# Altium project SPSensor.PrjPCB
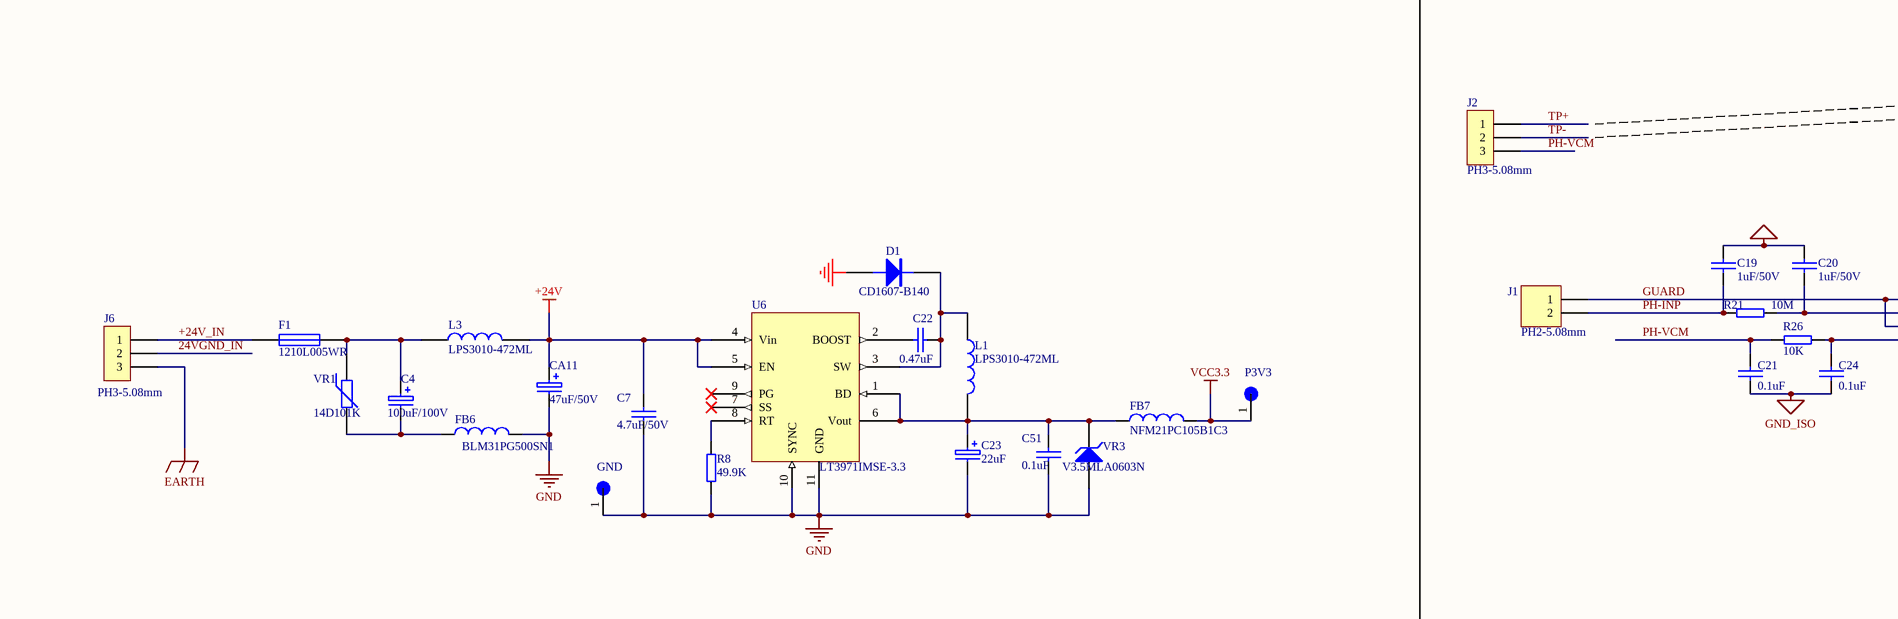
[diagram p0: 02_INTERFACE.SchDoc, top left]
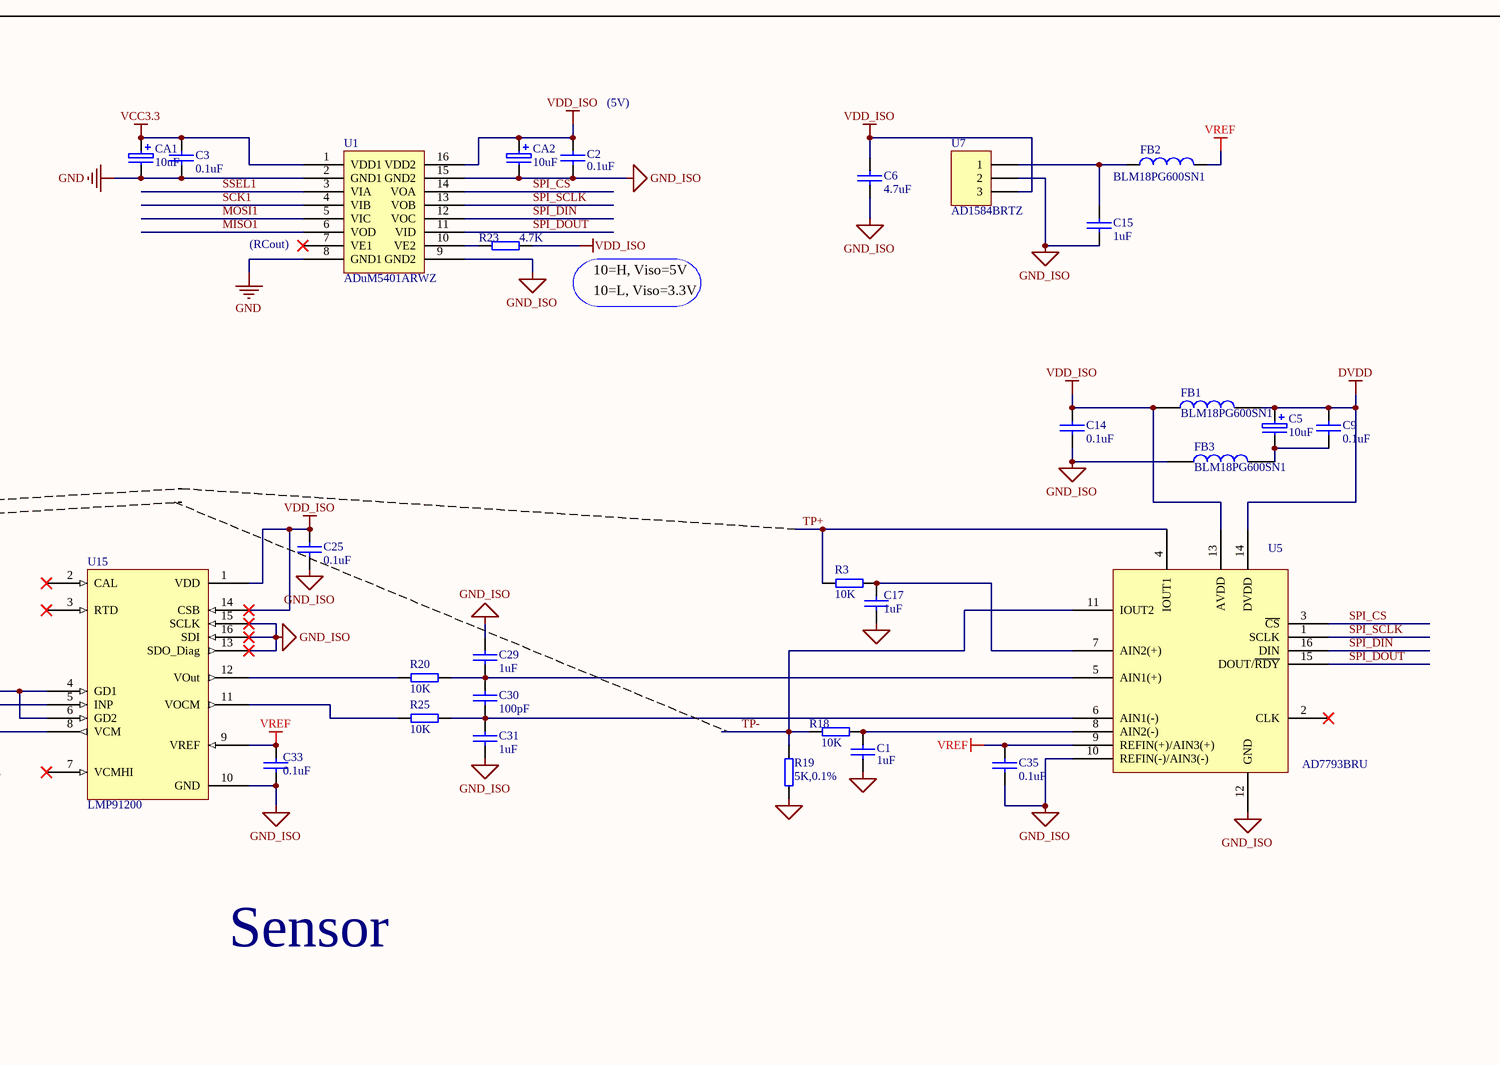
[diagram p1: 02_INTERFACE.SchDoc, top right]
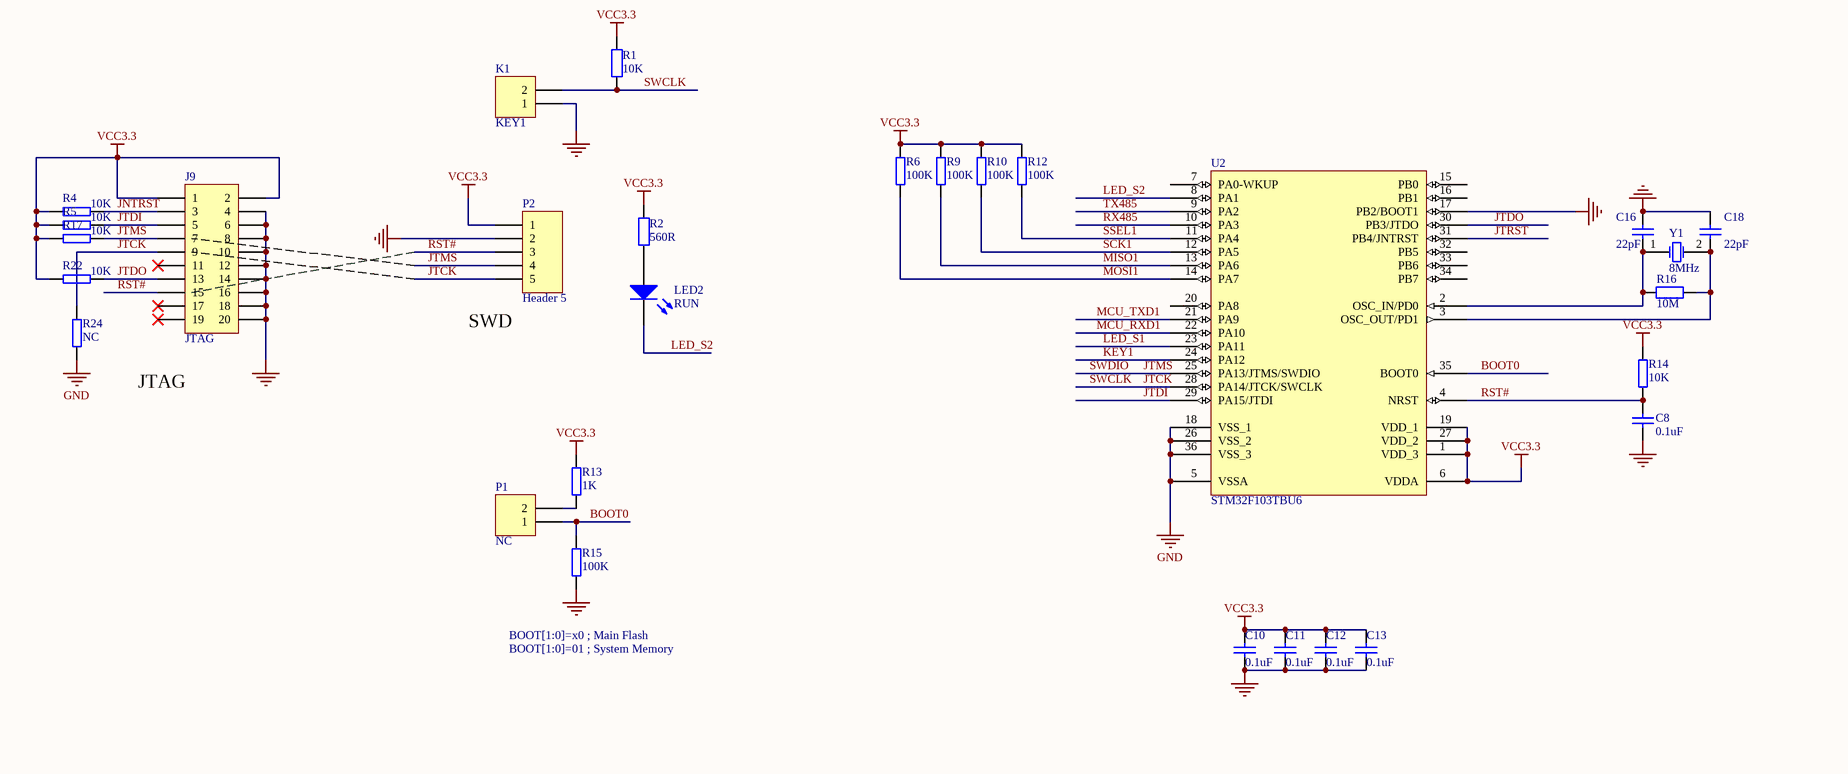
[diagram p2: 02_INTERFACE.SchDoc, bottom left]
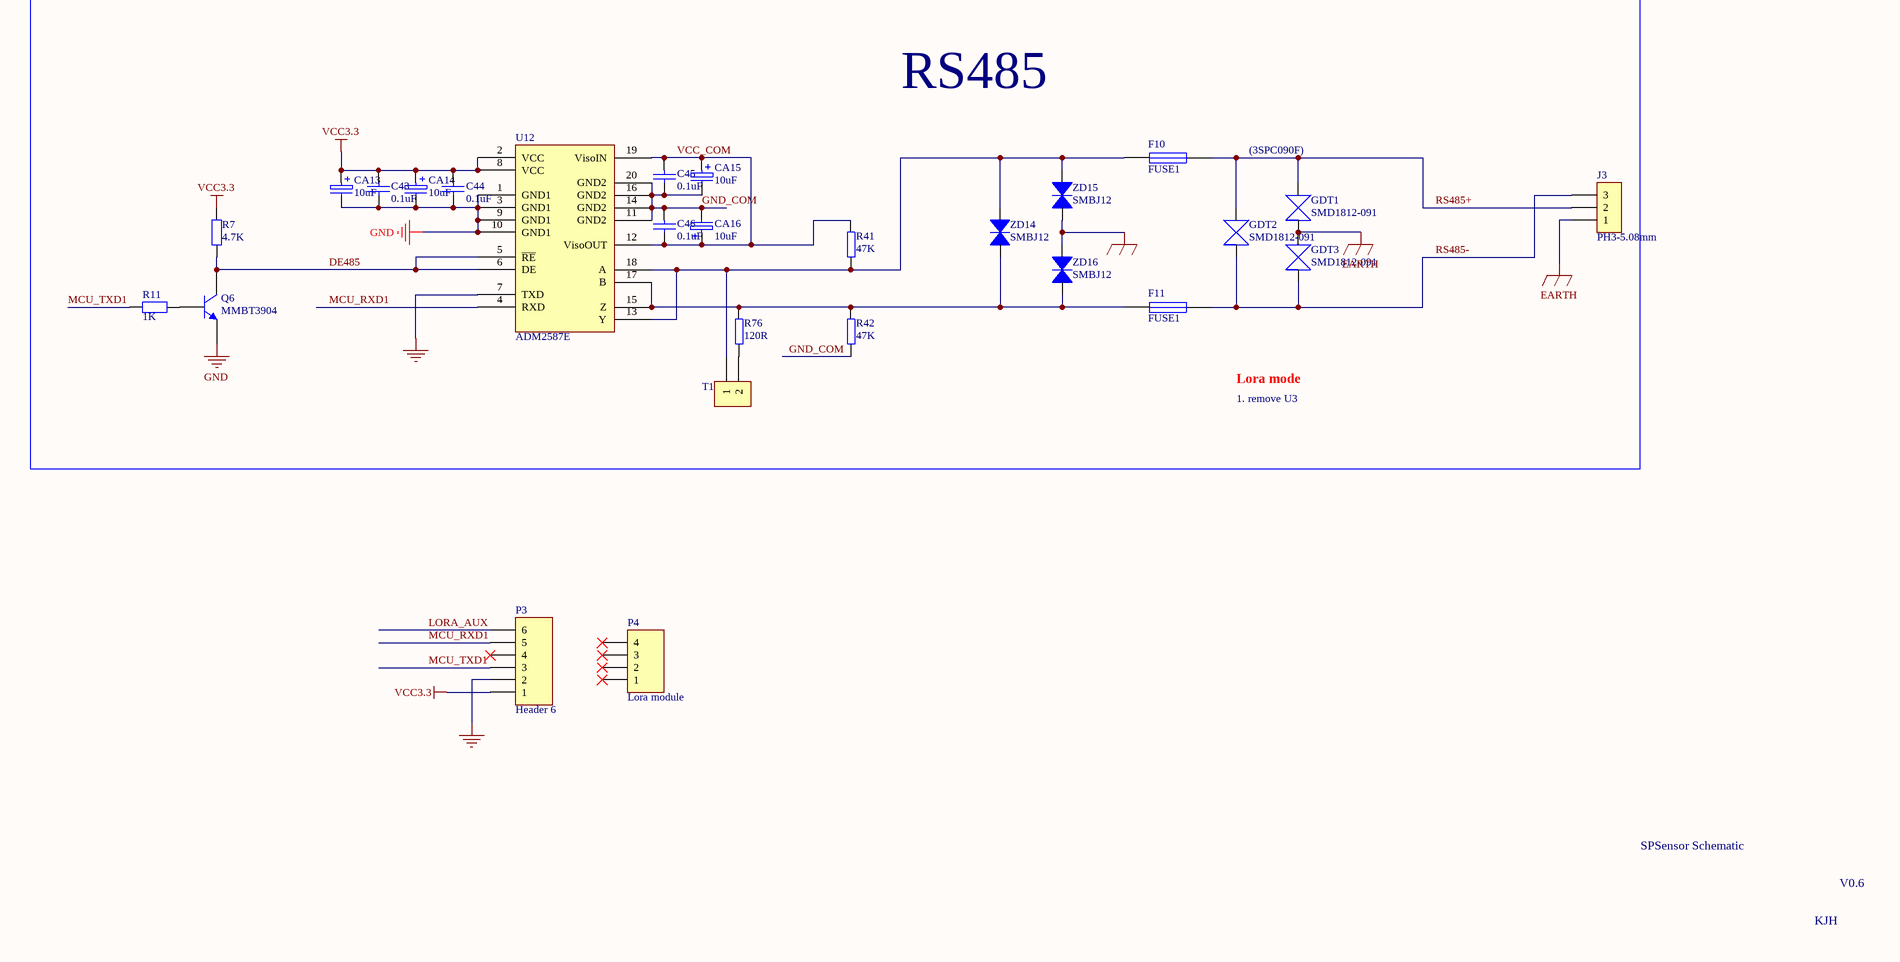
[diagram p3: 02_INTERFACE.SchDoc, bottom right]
1 sheet, 113 parts. Net scope: global (net labels, ports and power ports of the same name join across sheets).
Board file: SPSensor V0.7.PcbDoc

## Sheet 02_INTERFACE.SchDoc
size D; SheetNumber: 0; SheetTotal: 0

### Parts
C1  1uF  [SM0603]
C2  0.1uF  [SM0603]
C3  0.1uF  [SM0603]
C4  100uF/100V  [PCAP_3.5_8]
C5  10uF  [SM1206]
C6  4.7uF  [SM0603]
C7  4.7uF/50V  [SM1206]
C8  0.1uF  [SM0603]
C9  0.1uF  [SM0603]
C10  0.1uF  [SM0603]
C11  0.1uF  [SM0603]
C12  0.1uF  [SM0603]
C13  0.1uF  [SM0603]
C14  0.1uF  [SM0603]
C15  1uF  [SM0603]
C16  22pF  [SM0603]
C17  1uF  [SM0603]
C18  22pF  [SM0603]
C19  1uF/50V  [SM0603]
C20  1uF/50V  [SM0603]
C21  0.1uF  [SM0603]
C22  0.47uF  [SM0603]
C23  22uF  [SM1206]
C24  0.1uF  [SM0603]
C25  0.1uF  [SM0603]
C29  1uF  [SM0603]
C30  100pF  [SM0603]
C31  1uF  [SM0603]
C33  0.1uF  [SM0603]
C35  0.1uF  [SM0603]
C43  0.1uF  [SM0603]
C44  0.1uF  [SM0603]
C45  0.1uF  [SM0603]
C46  0.1uF  [SM0603]
C51  0.1uF  [SM0603]
CA1  10uF  [SM1206]
CA2  10uF  [SM1206]
CA11  47uF/50V  [D]
CA13  10uF  [SM1206]
CA14  10uF  [SM1206]
CA15  10uF  [SM1206]
CA16  10uF  [SM1206]
D1  CD1607-B140  [1206D]
F1  1210L005WR  [1808C]
F10  FUSE1  [SM0805]
F11  FUSE1  [SM0805]
FB1  BLM18PG600SN1  [SM0603]
FB2  BLM18PG600SN1  [SM0603]
FB3  BLM18PG600SN1  [SM0603]
FB6  BLM31PG500SN1  [1206]
FB7  NFM21PC105B1C3  [NFM21PC105]
GDT1  SMD1812-091  [1812]
GDT2  SMD1812-091  [1812]
GDT3  SMD1812-091  [1812]
GND  TestPoint  [test point]  (value not drawn)
J1  PH2-5.08mm  [PH2-5.08mm]
J2  PH3-5.08mm  [PH3-5.08mm]
J3  PH3-5.08mm  [PH3-5.08mm]
J6  PH3-5.08mm  [PH3-5.08mm]
J9  JTAG  [HDR2X10]
K1  KEY1  [HDR1x2]
L1  LPS3010-472ML  [LPS3010]
L3  LPS3010-472ML  [LPS3010]
LED2  RUN  [LED]
P1  NC  [SM0603]
P2  Header 5
P3  Header 6  [HDR1X6]
P3V3  TestPoint  [test point]  (value not drawn)
P4  Lora module
Q6  MMBT3904  [SOT23_N]
R1  10K  [SM0603]
R2  560R  [SM0603]
R3  10K  [SM0603]
R4  10K  [SM0603]
R5  10K  [SM0603]
R6  100K  [SM0603]
R7  4.7K  [SM0603]
R8  49.9K  [SM0603]
R9  100K  [SM0603]
R10  100K  [SM0603]
R11  1K  [SM0603]
R12  100K  [SM0603]
R13  1K  [SM0603]
R14  10K  [SM0603]
R15  100K  [SM0603]
R16  10M  [SM0603]
R17  10K  [SM0603]
R18  10K  [SM0603]
R19  5K,0.1%  [SM0603]
R20  10K  [SM0603]
R21  10M  [SM0603]
R22  10K  [SM0603]
R23  4.7K  [SM0603]
R24  NC  [SM0603]
R25  10K  [SM0603]
R26  10K  [SM0603]
R41  47K  [SM0603]
R42  47K  [SM0603]
R76  120R  [SM0603]
T1  (no value)  [SM0603]
U1  ADuM5401ARWZ  [ADUM1401]
U2  STM32F103TBU6  [VFQN36_V]
U5  AD7793BRU  [AD7793]
U6  LT3971IMSE-3.3  [LT3971]
U7  AD1584BRTZ  [SOT-23]
U12  ADM2587E  [SOL-20]
U15  LMP91200  [LMP91200]
VR1  14D101K  [RAD-0.3]
VR3  V3.5MLA0603N  [SM0603]
Y1  8MHz  [CY5.4X4.6]
ZD14  SMBJ12  [ZD]
ZD15  SMBJ12  [ZD]
ZD16  SMBJ12  [ZD]

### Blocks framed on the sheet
Sensor: C1-C3 C5 C6 C9 C14 C15 C17 C19-C21 C24 C25 C29-C31 C33 C35 CA1 CA2 FB1-FB3 J1 J2 R3 R18-R21 R23 R25 R26 U1 U5 U7 U15
RS485: C43-C46 CA13-CA16 F10 F11 GDT1-GDT3 J3 Q6 R7 R11 R41 R42 R76 T1 U12 ZD14-ZD16

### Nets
+24V: C7.1 CA11.1 L3.2 U6.4(Vin) U6.5(EN)
DVDD: C5.1 C9.1 FB1.2 U5.14(DVDD)
EARTH: GDT1.1 GDT3.2 J3.1 J6.3 ZD15.2 ZD16.1
GND: C3.1 C7.2 C8.2 C10.2 C11.2 C12.2 C13.2 C16.2 C18.2 C23.2 C43.2 C44.2 C51.2 CA1.2 CA11.2 CA13.2 CA14.2 D1.1(A) FB6.2 GND.1 J9.4 J9.6 J9.8 J9.10 J9.12 J9.14 J9.16 J9.18 J9.20 K1.1 P2.2 P3.2 Q6.2(E) R8.1 R15.1 R24.1 U1.2(GND1) U1.8(GND1) U2.5(VSSA) U2.17(PB2/BOOT1) U2.18(VSS_1) U2.26(VSS_2) U2.36(VSS_3) U6.10(SYNC) U6.11(GND) U12.1(GND1) U12.3(GND1) U12.7(TXD) U12.9(GND1) U12.10(GND1) VR3.1(A)
GND_ISO: C1.2 C2.2 C6.2 C14.2 C15.2 C17.2 C19.2 C20.2 C21.2 C24.2 C25.2 C29.1 C31.2 C33.2 C35.2 CA2.2 FB3.1 R19.1 U1.9(GND2) U1.15(GND2) U5.10(REFIN(-)/AIN3(-)) U5.12(GND) U7.2 U15.10(GND) U15.13(SDO_Diag) U15.15(SCLK) U15.16(SDI)
VCC3.3: C3.2 C10.1 C11.1 C12.1 C13.1 C43.1 C44.1 CA1.1 CA13.1 CA14.1 FB7.2 J9.1 J9.2 P2.1 P3.1 P3V3.1 R1.1 R2.1 R4.1 R5.1 R6.1 R7.2 R9.1 R10.1 R12.1 R13.1 R14.1 R17.1 R22.1 U1.1(VDD1) U2.1(VDD_3) U2.6(VDDA) U2.19(VDD_1) U2.27(VDD_2) U12.2(VCC) U12.8(VCC)
VDD_ISO: C2.1 C6.1 C14.1 C25.1 CA2.1 FB1.1 R23.2 U1.16(VDD2) U5.13(AVDD) U7.3 U15.1(VDD) U15.14(CSB)
VREF: C33.1 C35.1 FB2.2 U5.9(REFIN(+)/AIN3(+)) U15.9(VREF)
24VGND_IN: J6.2
+24V_IN: F1.1 J6.1
BOOT0: P1.1 R15.2 U2.35(BOOT0)
DE485: Q6.3(C) R7.1 U12.5(~{RE}) U12.6(DE)
GND_COM: C45.2 C46.1 CA15.2 CA16.2 R42.2 U12.11(GND2) U12.14(GND2) U12.16(GND2) U12.20(GND2)
GUARD: J1.1 U15.4(GD1) U15.6(GD2)
JNTRST: J9.3 R4.2
JTCK: J9.9 K1.2 P2.5 R1.2 R24.2 U2.28(PA14/JTCK/SWCLK)  [also labelled SWCLK]
JTDI: J9.5 R5.2 U2.29(PA15/JTDI)
JTDO: J9.13 R22.2 U2.30(PB3/JTDO)
JTMS: J9.7 P2.4 R17.2 U2.25(PA13/JTMS/SWDIO)  [also labelled SWDIO]
JTRST: U2.31(PB4/JNTRST)
KEY1: U2.24(PA12)
LED_S1: U2.23(PA11)
LED_S2: LED2.2(K) U2.8(PA1)
LORA_AUX: P3.6
MCU_RXD1: P3.5 U2.22(PA10) U12.4(RXD)
MCU_TXD1: P3.3 R11.1 U2.21(PA9)
MISO1: R9.2 U1.6(VOD) U2.13(PA6)
MOSI1: R6.2 U1.5(VIC) U2.14(PA7)
PH-INP: C19.1 J1.2 R21.1
PH-VCM: C21.1 J2.3 R26.1
RS485+: F10.2 GDT1.2 GDT2.2 J3.2
RS485-: F11.2 GDT2.1 GDT3.1 J3.3
RST#: C8.1 J9.15 P2.3 R14.2 U2.4(NRST)
RX485: U2.10(PA3)
SCK1: R10.2 U1.4(VIB) U2.12(PA5)
SPI_CS: U1.14(VOA) U5.3(~{CS})
SPI_DIN: U1.12(VOC) U5.16(DIN)
SPI_DOUT: U1.11(VID) U5.15(DOUT/~{RDY})
SPI_SCLK: U1.13(VOB) U5.1(SCLK)
SSEL1: R12.2 U1.3(VIA) U2.11(PA4)
TP+: J2.1 R3.1 U5.4(IOUT1)
TP-: J2.2 R18.1 R19.2 U5.11(IOUT2)
TX485: U2.9(PA2)
VCC_COM: C45.1 C46.2 CA15.1 CA16.1 R41.1 U12.12(VisoOUT) U12.19(VisoIN)
NetC1_1: C1.1 R18.2 U5.8(AIN2(-))
NetC4_1: C4.1 F1.2 L3.1 VR1.1
NetC4_2: C4.2 FB6.1 VR1.2
NetC5_2: C5.2 C9.2 FB3.2
NetC15_1: C15.1 FB2.1 U7.1
NetC16_1: C16.1 R16.1 U2.2(OSC_IN/PD0) Y1.1(OSC1)
NetC17_1: C17.1 R3.2 U5.7(AIN2(+))
NetC18_1: C18.1 R16.2 U2.3(OSC_OUT/PD1) Y1.2(OSC2)
NetC20_1: C20.1 R21.2 U15.5(INP)
NetC22_1: C22.1 U6.2(BOOST)
NetC22_2: C22.2 D1.2(K) L1.1 U6.3(SW)
NetC23_1: C23.1 C51.1 FB7.1 L1.2 U6.1(BD) U6.6(Vout) VR3.2(K)
NetC24_1: C24.1 R26.2 U15.8(VCM)
NetC29_2: C29.2 C30.1 R20.2 U5.5(AIN1(+))
NetC30_2: C30.2 C31.1 R25.2 U5.6(AIN1(-))
NetF10_1: F10.1 R41.2 T1.1 U12.13(Y) U12.18(A) ZD14.1 ZD15.1
NetF11_1: F11.1 R42.1 R76.1 U12.15(Z) U12.17(B) ZD14.2 ZD16.2
NetLED2_1: LED2.1(A) R2.2
NetP1_2: P1.2 R13.2
NetQ6_1: Q6.1(B) R11.2
NetR8_2: R8.2 U6.8(RT)
NetR20_1: R20.1 U15.12(VOut)
NetR23_1: R23.1 U1.10(VE2)
NetR25_1: R25.1 U15.11(VOCM)
NetR76_2: R76.2 T1.2

Not connected (* = marked no-connect by the designer): J9 11* 17* 19*; P3 4*; P4 1* 2* 3* 4*; U1 7(VE1)*; U2 7(PA0-WKUP) 15(PB0) 16(PB1) 20(PA8) 32(PB5) 33(PB6) 34(PB7); U5 2(CLK)*; U6 7(SS)* 9(PG)*; U15 2(CAL)* 3(RTD)* 7(VCMHI)*

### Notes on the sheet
- (near C2) (5V)
- (near U1) (RCout)
- 10=H, Viso=5V
- 10=L, Viso=3.3V
- (near P2) SWD
- JTAG
- (near GDT1) (3SPC090F)
- BOOT[1:0]=x0 ; Main Flash
- BOOT[1:0]=01 ; System Memory
- 1. remove U3
- Lora mode
- SPSensor Schematic
- KJH
- V0.6

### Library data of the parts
C1 C6 C7 C9 C14 C15 C17 C19-C22 C24 C25 C29-C31 C33 C35 C51 = CAP: Capacitor
C2 C3 C43-C46 = CA: 电容
C4 = C: Capacitor
C5 CA11 CA13-CA16 = CAPE: 极性电容
C8 = Cap: Capacitor, X7R Ceramic
C10-C13 = Cap: Capacitor
C16 C18 = Cap: Capacitor; Value: 0.1uF
C23 = C: 极性电容
CA1 CA2 = CAPE: Capacitor
D1 = DIODE
F1 = FUSE1: Fuse, 50mA
F10 F11 = FUSE1: Fuse
FB1 FB3 L1 L3 = INDUCTOR
FB2 FB6 FB7 = Inductor: Code_IEC: 1005; Value: 10mH
GDT1-GDT3 = BT90
J1 K1 = Header 2: Header, 2-Pin
J2 J3 J6 = CON3: Connector
J9 = Header 10X2: Header, 10-Pin, Dual row
LED2 = LED0: Typical INFRARED GaAs LED
P1 = Header: Header, 2-Pin, 2.54mm, 排针
P2 = Header 5: Header, 5-Pin
P3 = Header 6: Header, 6-Pin
P4 = Header 4: Header, 4-Pin
Q6 = MMBT3904: NPN Switching Transistor
R1 R2 R7 R16 = Res2: Resistor; Value: 1K
R3-R6 R9 R10 R12 R17-R20 R22 R24-R26 = RES: 电阻
R8 R13-R15 R23 R41 R42 R76 = RE: 电阻
R11 = Res2: Resistor
R21 = RES: resistor
T1 = CON2: Connector
U1 = ADUM1401: 1Mbps Data Rate, 100ns Propagation delay
U2 = STM32F103T8U6: STM32 ARM-based 32-bit MCU with 64 Kbytes Flash, 36-pin VFQFPN, Industrial Temperature
U5 = AD7793
U6 = LT3971
U7 = Header 3: 4.096V reference
VR1 = Res Varistor: Varistor (Voltage-Sensitive Resistor)
VR3 = D Zener: Zener Diode
Y1 = XTAL: Crystal Oscillator
ZD14-ZD16 = SMBJ: 瞬变抑制二极管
